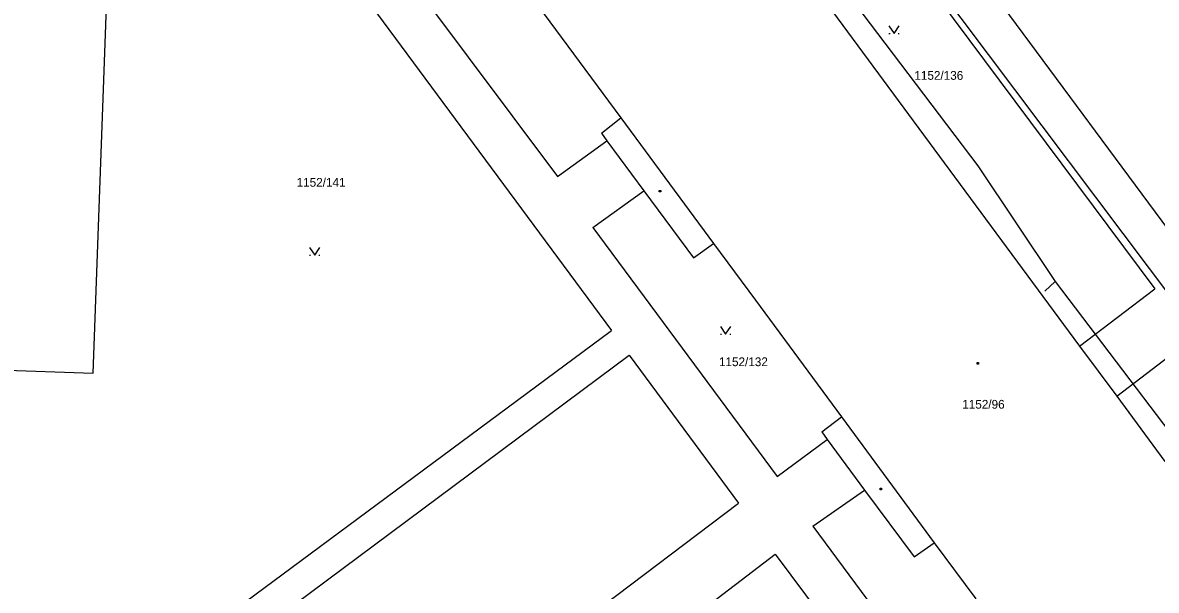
# Model space of a CAD drawing. Extents: x -609709 to -609357, y -1051535 to -1051131.
# Drawn here: x -609585.1 to -609530.2, y -1051388.6 to -1051361.1 of the extents above; entities that cross this region are included whole.
import ezdxf

# ---------------------------------------------------------------- set-up
doc = ezdxf.new("R2010")
doc.units = 0
doc.layers.add('Vrstva 10', color=7, linetype='Continuous')
doc.layers.add('Vrstva 12', color=7, linetype='Continuous')

msp = doc.modelspace()

# ---------------------------------------------------------------- linework, layer by layer
at = {"layer": 'Vrstva 10'}
for p, q in [((-609581.79, -1051300.71), (-609506.66, -1051402.14)), ((-609595.06, -1051324), (-609556.61, -1051376.01)), ((-609570.66, -1051353.26), (-609559.22, -1051368.54)), ((-609581.73, -1051378.07), (-609580.88, -1051355.01)), ((-609543.55, -1051356.19), (-609530.27, -1051373.99)), ((-609547.13, -1051358.87), (-609540.48, -1051367.88)), ((-609560.47, -1051359.86), (-609556.16, -1051365.7)), ((-609543.16, -1051361.245), (-609542.91, -1051361.62)), ((-609542.91, -1051361.62), (-609542.66, -1051361.245)), ((-609543.16, -1051361.62), (-609543.11, -1051361.62)), ((-609542.71, -1051361.62), (-609542.66, -1051361.62)), ((-609557.1, -1051366.44), (-609556.16, -1051365.7)), ((-609556.16, -1051365.7), (-609551.67, -1051371.79)), ((-609557.1, -1051366.44), (-609556.83, -1051366.82)), ((-609559.22, -1051368.54), (-609556.83, -1051366.82)), ((-609556.83, -1051366.82), (-609555.04, -1051369.24)), ((-609540.48, -1051367.88), (-609533.92, -1051376.76)), ((-609557.51, -1051371.01), (-609555.04, -1051369.24)), ((-609555.04, -1051369.24), (-609552.63, -1051372.48)), ((-609554.295, -1051369.215), (-609554.22, -1051369.215)), ((-609554.295, -1051369.29), (-609554.295, -1051369.215)), ((-609554.22, -1051369.29), (-609554.295, -1051369.29)), ((-609554.22, -1051369.215), (-609554.22, -1051369.29)), ((-609557.51, -1051371.01), (-609548.58, -1051383.08)), ((-609571.24, -1051371.975), (-609570.99, -1051372.35)), ((-609570.99, -1051372.35), (-609570.74, -1051371.975)), ((-609552.63, -1051372.48), (-609551.67, -1051371.79)), ((-609551.67, -1051371.79), (-609549.63, -1051374.54)), ((-609571.24, -1051372.35), (-609571.19, -1051372.35)), ((-609570.79, -1051372.35), (-609570.74, -1051372.35)), ((-609533.92, -1051376.76), (-609530.27, -1051373.99)), ((-609549.63, -1051374.54), (-609545.46, -1051380.19)), ((-609551.33, -1051375.805), (-609551.08, -1051376.18)), ((-609551.08, -1051376.18), (-609550.83, -1051375.805)), ((-609590.06, -1051400.76), (-609556.61, -1051376.01)), ((-609551.33, -1051376.18), (-609551.28, -1051376.18)), ((-609550.88, -1051376.18), (-609550.83, -1051376.18)), ((-609532.12, -1051379.19), (-609528.48, -1051376.39)), ((-609533.92, -1051376.76), (-609532.12, -1051379.19)), ((-609589.45, -1051402.27), (-609555.75, -1051377.2)), ((-609555.75, -1051377.2), (-609550.46, -1051384.37)), ((-609593.82, -1051377.63), (-609581.73, -1051378.07)), ((-609538.89, -1051377.555), (-609538.815, -1051377.555)), ((-609538.89, -1051377.63), (-609538.89, -1051377.555)), ((-609538.815, -1051377.63), (-609538.89, -1051377.63)), ((-609538.815, -1051377.555), (-609538.815, -1051377.63)), ((-609532.12, -1051379.19), (-609529.79, -1051382.35)), ((-609546.41, -1051380.91), (-609545.46, -1051380.19)), ((-609545.46, -1051380.19), (-609540.97, -1051386.28)), ((-609548.58, -1051383.08), (-609546.15, -1051381.28)), ((-609546.41, -1051380.91), (-609546.15, -1051381.28)), ((-609546.15, -1051381.28), (-609544.34, -1051383.73)), ((-609546.85, -1051385.48), (-609544.34, -1051383.73)), ((-609544.34, -1051383.73), (-609541.94, -1051386.96)), ((-609543.595, -1051383.645), (-609543.52, -1051383.645)), ((-609543.595, -1051383.72), (-609543.595, -1051383.645)), ((-609543.52, -1051383.72), (-609543.595, -1051383.72)), ((-609543.52, -1051383.645), (-609543.52, -1051383.72)), ((-609571.71, -1051400.42), (-609550.46, -1051384.37)), ((-609546.85, -1051385.48), (-609539.99, -1051394.71)), ((-609541.94, -1051386.96), (-609540.97, -1051386.28)), ((-609540.97, -1051386.28), (-609538.95, -1051389)), ((-609553.88, -1051390.81), (-609548.67, -1051386.83)), ((-609548.67, -1051386.83), (-609537.77, -1051401.44))]:
    msp.add_line(p, q, dxfattribs=at)
at = {"layer": 'Vrstva 12'}
for points in [[(-609615.546, -1051325.052), (-609614.108, -1051326.974), (-609589.099, -1051308.266), (-609582.815, -1051303.565), (-609514.844, -1051393.856), (-609499.807, -1051382.785), (-609467.693, -1051377.467)], [(-609545.59, -1051359.13), (-609538.86, -1051368.03), (-609535.11, -1051373.63), (-609535.613, -1051374.09)], [(-609535.11, -1051373.63), (-609526.59, -1051384.83), (-609524.39, -1051388.15), (-609524.969, -1051388.565)]]:
    msp.add_lwpolyline(points, dxfattribs=at)

# ---------------------------------------------------------------- texts
at = {"layer": 'Vrstva 10'}
for s, p in [('1152/136', (-609541.93, -1051363.86)), ('1152/141', (-609571.868, -1051369.04)), ('1152/132', (-609551.4, -1051377.73)), ('1152/96', (-609539.61, -1051379.79))]:
    msp.add_text(s, height=0.425, dxfattribs=at).set_placement(p)

doc.saveas('drawing.dxf')
